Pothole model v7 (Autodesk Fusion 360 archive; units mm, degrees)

design "Pothole model" references "Tyre", "Plane", "Plane 3", "Plane 4", "Servo", "Tyre Holder", "Plane 2", "Pipe"
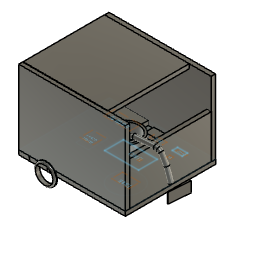
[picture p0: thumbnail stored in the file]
sketch "Sketch1" plane through (0, 0, 0) normal (0, 0, 1) x axis (1, 0, 0)
  line L1 (244.3707, 0) -> (0, 0)
  line L2 (244.3707, 207.569) -> (244.3707, 0)
  line L3 (0, 207.569) -> (244.3707, 207.569)
  line L4 (0, 0) -> (0, 207.569)
  point P1 (0, 0)
  point P2 (0, 0)
  horizontal L1
  vertical L2
  horizontal L3
  vertical L4
  coincident P1 P2
extrude "Extrude1" new body sketch "Sketch1" along normal blind 10
cylinder_primitive "CylinderPrimitive1" Height 100 Diameter 70
move_face "MoveFace1"
shell "Shell1" innerThickness 5
step "TorusPrimitive" MinorDiameter 10 MajorDiameter 42.32
shell "Shell2" innerThickness 5
delete_face "DeleteFace1"
sketch "Sketch4" plane through (0, 0, 10) normal (0, 0, 1) x axis (-1, 0, 0)
  line L1 (-244.3707, 0) -> (0, 0)
  line L2 (-244.3707, -207.569) -> (-244.3707, 0)
  line L3 (0, -207.569) -> (-244.3707, -207.569)
  line L4 (0, 0) -> (0, -207.569)
  line L5 (-50.8328, -80) -> (-80, -80)
  line L6 (-50.8328, -124.9358) -> (-50.8328, -80)
  line L7 (-80, -124.9358) -> (-50.8328, -124.9358)
  line L8 (-80, -80) -> (-80, -124.9358)
  circle C1 centre (-188.7209, -56.7574) radius 35
  horizontal L5
  vertical L6
  horizontal L7
  vertical L8
extrude "Extrude2" add sketch "Sketch4" profile of L5 L6 L7 L8 along normal blind 5
sketch "Sketch5" plane through (0, 0, 10) normal (0, 0, 1) x axis (-1, 0, 0)
  line L1 (-80, -80) -> (-80, -124.9358)
  line L2 (-50.8328, -80) -> (-80, -80)
  line L3 (-50.8328, -124.9358) -> (-50.8328, -80)
  line L4 (-80, -124.9358) -> (-50.8328, -124.9358)
  line L5 (-244.3707, 0) -> (0, 0)
  line L6 (-244.3707, -207.569) -> (-244.3707, 0)
  line L7 (0, -207.569) -> (-244.3707, -207.569)
  line L8 (0, 0) -> (0, -207.569)
  line L9 (-100, -97.2076) -> (-177.6183, -97.2076)
  line L10 (-100, -140) -> (-100, -97.2076)
  line L11 (-177.6183, -140) -> (-100, -140)
  line L12 (-177.6183, -97.2076) -> (-177.6183, -140)
  circle C1 centre (-188.7209, -56.7574) radius 35
  horizontal L9
  vertical L10
  horizontal L11
  vertical L12
extrude "Extrude3" add sketch "Sketch5" profile of L9 L10 L11 L12 along normal blind 5
extrude "Extrude4" add blind 10
sketch "Sketch7" plane through (0, 0, 15) normal (0, 0, 1) x axis (-1, 0, 0)
  dimension "d15" = 10
  dimension "d16" = 6
component_insert "Component Insert6"
component_insert "Component Insert7"
component_insert "Component Insert8"
component_insert "Component Insert9"
component_insert "Component Insert10"
sketch "Sketch8" plane through (0, 0, 10) normal (0, 0, 1) x axis (-1, 0, 0)
  dimension "d17" = 10
sketch "Sketch9" plane through (0, 0, 10) normal (0, 0, 1) x axis (-1, 0, 0)
  line L1 (-120, -170) -> (-160, -170)
  line L2 (-120, -190) -> (-120, -170)
  line L3 (-160, -190) -> (-120, -190)
  line L4 (-160, -170) -> (-160, -190)
  horizontal L1
  vertical L2
  horizontal L3
  vertical L4
extrude "Extrude5" add sketch "Sketch9" along normal blind 10
sketch "Sketch10" plane through (0, 0, 10) normal (0, 0, 1) x axis (-1, 0, 0)
  dimension "d20" = 10
  dimension "d21" = 10
extrude "Extrude6" add sketch "Sketch10" along normal blind 20
cylinder_primitive "CylinderPrimitive2" Height 2.5 Diameter 4.46
cylinder_primitive "CylinderPrimitive3" Height 2.5 Diameter 4.84
sketch "Sketch13" plane through (0, 0, 10) normal (0, 0, 1) x axis (-1, 0, 0)
  line L1 (-174.31, -170) -> (-220, -170)
  line L2 (-174.31, -190.1564) -> (-174.31, -170)
  line L3 (-220, -190.1564) -> (-174.31, -190.1564)
  line L4 (-220, -170) -> (-220, -190.1564)
  horizontal L1
  vertical L2
  horizontal L3
  vertical L4
extrude "Extrude7" add sketch "Sketch13" along normal blind 5
sketch "Sketch14" plane through (0, 0, 10) normal (0, 0, 1) x axis (-1, 0, 0)
  line L1 (-177.201, -175) -> (-200, -175)
  line L2 (-177.201, -186.9937) -> (-177.201, -175)
  line L3 (-200, -186.9937) -> (-177.201, -186.9937)
  line L4 (-200, -175) -> (-200, -186.9937)
  horizontal L1
  vertical L2
  horizontal L3
  vertical L4
box_primitive "BoxPrimitive1" DistanceX 10 DistanceY 25 DistanceZ 5 OffsetDistanceX 0 OffsetDistanceY 0
sketch "Sketch16" plane through (0, 0, 10) normal (0, 0, 1) x axis (-1, 0, 0)
  dimension "d35" = 10
  dimension "d36" = 10
  dimension "d37" = 5
  dimension "d38" = 5
component_insert "Component Insert11"
component_insert "Component Insert14"
component_insert "Component Insert15"
component_insert "Component Insert16"
component_insert "Component Insert17"

design "Plane 2"
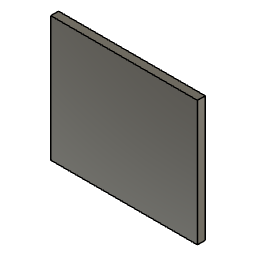
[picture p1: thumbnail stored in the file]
sketch "Sketch1" plane through (0, 0, 0) normal (0, 1, 0) x axis (1, 0, 0)
  line L1 (187.57, 0) -> (0, 0)
  line L2 (187.57, -160) -> (187.57, 0)
  line L3 (0, -160) -> (187.57, -160)
  line L4 (0, 0) -> (0, -160)
  point P1 (0, 0)
  point P2 (0, 0)
  point P3 (187.57, 0)
  point P5 (0, -160)
  horizontal L1
  vertical L2
  horizontal L3
  vertical L4
  coincident P1 P2
  dimension "d1" distance P2 P3 = 187.57
  dimension "d2" distance P2 P5 = 160
extrude "Extrude1" new body sketch "Sketch1" along normal blind 10

design "Tyre Holder" references "Small tyre"
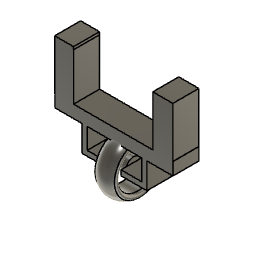
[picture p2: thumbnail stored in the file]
sketch "Sketch1" plane through (0, 0, 0) normal (0, 1, 0) x axis (1, 0, 0)
  line L1 (26.7266, -33.9417) -> (19.4439, -33.9417)
  line L2 (26.7266, -15.4922) -> (26.7266, -33.9417)
  line L3 (19.4439, -15.4922) -> (26.7266, -15.4922)
  line L4 (19.4439, -33.9417) -> (19.4439, -15.4922)
  horizontal L1
  vertical L2
  horizontal L3
  vertical L4
extrude "Extrude1" new body sketch "Sketch1" along normal blind 10
sketch "Sketch2" plane through (0, 0, 0) normal (0, 1, 0) x axis (1, 0, 0)
  line L1 (65, -35.1686) -> (57.2809, -35.1686)
  line L2 (65, -15) -> (65, -35.1686)
  line L3 (57.2809, -15) -> (65, -15)
  line L4 (57.2809, -35.1686) -> (57.2809, -15)
  horizontal L1
  vertical L2
  horizontal L3
  vertical L4
extrude "Extrude2" new body sketch "Sketch2" along normal blind 10
move_face "MoveFace1"
sketch "Sketch3" plane through (0, 0, 0) normal (0, 1, 0) x axis (1, 0, 0)
  line L1 (65.0384, -15.7821) -> (19.5015, -15.7821)
  line L2 (65.0384, -10.957) -> (65.0384, -15.7821)
  line L3 (19.5015, -10.957) -> (65.0384, -10.957)
  line L4 (19.5015, -15.7821) -> (19.5015, -10.957)
  horizontal L1
  vertical L2
  horizontal L3
  vertical L4
extrude "Extrude3" add sketch "Sketch3" along normal blind 10
sketch "Sketch4" plane through (0, 0, 0) normal (0, 1, 0) x axis (1, 0, 0)
  line L1 (26.7138, -34.9681) -> (19.4586, -34.9681)
  line L2 (26.7138, -33.3054) -> (26.7138, -34.9681)
  line L3 (19.4586, -33.3054) -> (26.7138, -33.3054)
  line L4 (19.4586, -34.9681) -> (19.4586, -33.3054)
  horizontal L1
  vertical L2
  horizontal L3
  vertical L4
extrude "Extrude4" add sketch "Sketch4" along normal blind 10
sketch "Sketch5" plane through (0, 0, 0) normal (0, 1, 0) x axis (1, 0, 0)
  line L1 (32, -11) -> (30, -11)
  line L2 (32, -1) -> (32, -11)
  line L3 (30, -1) -> (32, -1)
  line L4 (30, -11) -> (30, -1)
  horizontal L1
  vertical L2
  horizontal L3
  vertical L4
extrude "Extrude5" add sketch "Sketch5" along normal blind 10
sketch "Sketch6" plane through (0, 0, 0) normal (0, 1, 0) x axis (1, 0, 0)
  line L1 (53, -11) -> (55, -11)
  line L2 (53, -1) -> (53, -11)
  line L3 (55, -1) -> (53, -1)
  line L4 (55, -11) -> (55, -1)
  horizontal L1
  vertical L2
  horizontal L3
  vertical L4
extrude "Extrude6" add sketch "Sketch6" along normal blind 10
sketch "Sketch7" plane through (0, 0, 0) normal (0, 1, 0) x axis (1, 0, 0)
  line L1 (40, -3) -> (32, -3)
  line L2 (40, -1) -> (40, -3)
  line L3 (32, -1) -> (40, -1)
  line L4 (32, -3) -> (32, -1)
  horizontal L1
  vertical L2
  horizontal L3
  vertical L4
extrude "Extrude7" add sketch "Sketch7" along normal blind 10
sketch "Sketch8" plane through (0, 0, 0) normal (0, 1, 0) x axis (1, 0, 0)
  line L1 (53, -3) -> (45, -3)
  line L2 (53, -1) -> (53, -3)
  line L3 (45, -1) -> (53, -1)
  line L4 (45, -3) -> (45, -1)
  horizontal L1
  vertical L2
  horizontal L3
  vertical L4
extrude "Extrude8" add sketch "Sketch8" along normal blind 10
sketch "Sketch9" plane through (0, 0, 0) normal (0, 1, 0) x axis (1, 0, 0)
  line L1 (40, -3) -> (39, -3)
  line L2 (40, -1) -> (40, -3)
  line L3 (39, -1) -> (40, -1)
  line L4 (39, -3) -> (39, -1)
  horizontal L1
  vertical L2
  horizontal L3
  vertical L4
extrude "Extrude9" cut sketch "Sketch9" along normal blind 10
component_insert "Component Insert"

design "Plane 4"
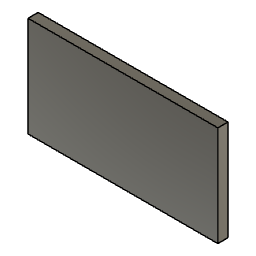
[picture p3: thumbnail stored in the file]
sketch "Sketch1" plane through (0, 0, 0) normal (0, 1, 0) x axis (1, 0, 0)
  line L1 (187.57, 0) -> (0, 0)
  line L2 (187.57, -99) -> (187.57, 0)
  line L3 (0, -99) -> (187.57, -99)
  line L4 (0, 0) -> (0, -99)
  point P1 (0, 0)
  point P2 (0, 0)
  point P3 (187.57, 0)
  point P5 (0, -99)
  horizontal L1
  vertical L2
  horizontal L3
  vertical L4
  coincident P1 P2
  dimension "d1" distance P2 P3 = 187.57
  dimension "d2" distance P2 P5 = 99
extrude "Extrude1" new body sketch "Sketch1" along normal blind 10

design "Small tyre"
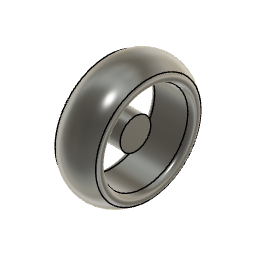
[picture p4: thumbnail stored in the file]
sketch "Sketch1" plane through (0, 0, 0) normal (1, 0, 0) x axis (0, 1, 0)
  circle C1 centre (24.9666, 12.7062) radius 12.6513
extrude "Extrude1" new body sketch "Sketch1" along normal blind 10
hole "Hole1" HoleDepth 10 HoleDiameter 10 TipAngle 118 CBDepth 1 CBDiameter 16
delete_face "DeleteFace1"
fillet "Fillet1" radius 5.5
fillet "Fillet2" radius 1
fillet "Fillet3" radius 1
sketch "Sketch2" plane through (0, 0, 0) normal (1, 0, 0) x axis (0, 1, 0)
  circle C1 centre (25, 13) radius 2.8284
extrude "Extrude2" new body sketch "Sketch2" along normal blind 5
sketch "Sketch3" plane through (0, 0, 0) normal (1, 0, 0) x axis (0, 1, 0)
sketch "Sketch4" plane through (0, 0, 0) normal (1, 0, 0) x axis (0, 1, 0)
move_face "MoveFace1"
move_face "MoveFace2"
move_face "MoveFace3"
move_face "MoveFace4"
move_face "MoveFace5"
move_face "MoveFace6"
fillet "Fillet4" radius 5

design "Plane"
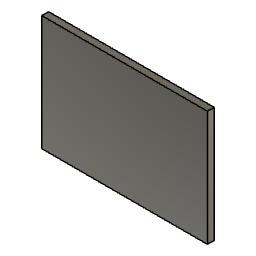
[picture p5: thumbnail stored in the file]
sketch "Sketch1" plane through (0, 0, 0) normal (0, 1, 0) x axis (1, 0, 0)
  line L1 (244.37, 0) -> (0, 0)
  line L2 (244.37, -170) -> (244.37, 0)
  line L3 (0, -170) -> (244.37, -170)
  line L4 (0, 0) -> (0, -170)
  point P1 (0, 0)
  point P2 (0, 0)
  point P3 (244.37, 0)
  horizontal L1
  vertical L2
  horizontal L3
  vertical L4
  coincident P1 P2
  dimension "d1" distance P2 P3 = 244.37
extrude "Extrude1" new body sketch "Sketch1" along normal blind 10

design "Servo"
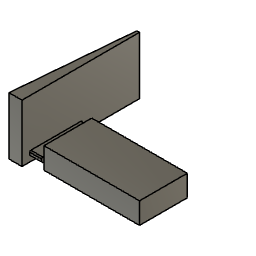
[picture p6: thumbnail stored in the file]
sketch "Sketch1" plane through (0, 0, 0) normal (0, 0, 1) x axis (1, 0, 0)
  line L1 (40, 0) -> (0, 0)
  line L2 (40, 20) -> (40, 0)
  line L3 (0, 20) -> (40, 20)
  line L4 (0, 0) -> (0, 20)
  point P1 (0, 0)
  point P2 (0, 0)
  horizontal L1
  vertical L2
  horizontal L3
  vertical L4
  coincident P1 P2
extrude "Extrude1" new body sketch "Sketch1" along normal blind 8.9
sketch "Sketch2" plane through (0, 0, 0) normal (1, 0, 0) x axis (0, 1, 0)
  line L1 (-1, 5) -> (21, 5)
  line L2 (-1, 3) -> (-1, 5)
  line L3 (21, 3) -> (-1, 3)
  line L4 (21, 5) -> (21, 3)
  horizontal L1
  vertical L2
  horizontal L3
  vertical L4
extrude "Extrude2" new body sketch "Sketch2" along normal blind 0 and against normal blind 5
cylinder_primitive "CylinderPrimitive1" Height -5 Diameter 1.78
fillet "Fillet1" radius 0.5
fillet "Fillet2" radius 0.5
fillet "Fillet3" radius 0.5
fillet "Fillet4" radius 0.5
sketch "Sketch4" plane through (0, 0, 0) normal (1, 0, 0) x axis (0, 1, 0)
  line L1 (-4.2128, 25) -> (45, 25)
  line L2 (-4.2128, 0.9481) -> (-4.2128, 25)
  line L3 (45, 0.9481) -> (-4.2128, 0.9481)
  line L4 (45, 25) -> (45, 0.9481)
  horizontal L1
  vertical L2
  horizontal L3
  vertical L4
extrude "Extrude3" add sketch "Sketch4" against normal blind 9 and against normal blind 5
move_face "MoveFace1"

design "Tyre"
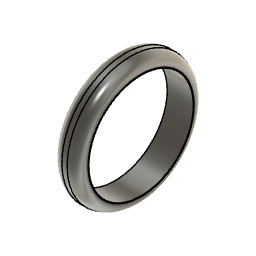
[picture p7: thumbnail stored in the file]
sketch "Sketch1" plane through (0, 0, 0) normal (1, 0, 0) x axis (0, 1, 0)
  circle C1 centre (25, 25) radius 24.2814
extrude "Extrude1" new body sketch "Sketch1" along normal blind 15
fillet "Fillet1" radius 4
shell "Shell1" innerThickness 30
hole "Hole1" HoleDepth 10 HoleDiameter 40 TipAngle 118
fillet "Fillet2" radius 4

design "Pipe"
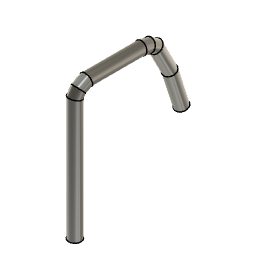
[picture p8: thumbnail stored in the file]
sketch "Sketch1" plane through (0, 0, 0) normal (1, 0, 0) x axis (0, 1, 0)
  curve K1 (130, 100) -> (0, 0)
sketch "Sketch2" plane through (0, 0, 0) normal (1, 0, 0) x axis (0, 1, 0)
sketch "Sketch3" plane through (0, 0, 0) normal (1, 0, 0) x axis (0, 1, 0)
  line L1 (0, 100) -> (0, 0)
  line L2 (2.9083, 104.4384) -> (0, 100)
  line L3 (9.5215, 107.8674) -> (2.9083, 104.4384)
  line L4 (15, 107.8674) -> (9.5215, 107.8674)
  line L5 (23.7275, 107.8674) -> (15, 107.8674)
  line L6 (35, 107.8674) -> (23.7275, 107.8674)
  line L7 (53.8541, 107.8674) -> (35, 107.8674)
  line L8 (60.4247, 106.6341) -> (53.8541, 107.8674)
  line L9 (65.7711, 103.2215) -> (60.4247, 106.6341)
  line L10 (70, 95) -> (65.7711, 103.2215)
  line L11 (73.8276, 87.5586) -> (70, 95)
  line L12 (77.4486, 80.5189) -> (73.8276, 87.5586)
  line L13 (83.6305, 61.3601) -> (77.4486, 80.5189)
  line L14 (85.608, 55.2315) -> (83.6305, 61.3601)
  line L15 (87.119, 50.5486) -> (85.608, 55.2315)
  point P1 (0, 0)
  point P2 (0, 0)
  coincident P1 P2
  vertical L1
  perpendicular L1 L4
  parallel L4 L5
  parallel L5 L6
  parallel L6 L7
  parallel L10 L11
  parallel L10 L12
  parallel L13 L14
  parallel L14 L15
pipe "Pipe2" SectionSize 10 SectionThickness 2.5

design "Plane 3"
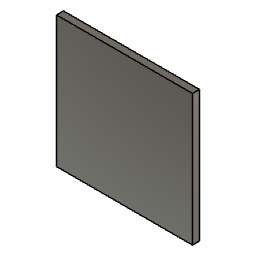
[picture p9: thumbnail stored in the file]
sketch "Sketch1" plane through (0, 0, 0) normal (0, 1, 0) x axis (1, 0, 0)
  line L1 (194.37, 0) -> (0, 0)
  line L2 (194.37, -187.57) -> (194.37, 0)
  line L3 (0, -187.57) -> (194.37, -187.57)
  line L4 (0, 0) -> (0, -187.57)
  point P1 (0, 0)
  point P2 (0, 0)
  point P3 (194.37, 0)
  point P5 (0, -187.57)
  horizontal L1
  vertical L2
  horizontal L3
  vertical L4
  coincident P1 P2
  dimension "d1" distance P2 P3 = 194.37
  dimension "d2" distance P2 P5 = 187.57
extrude "Extrude1" new body sketch "Sketch1" along normal blind 10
